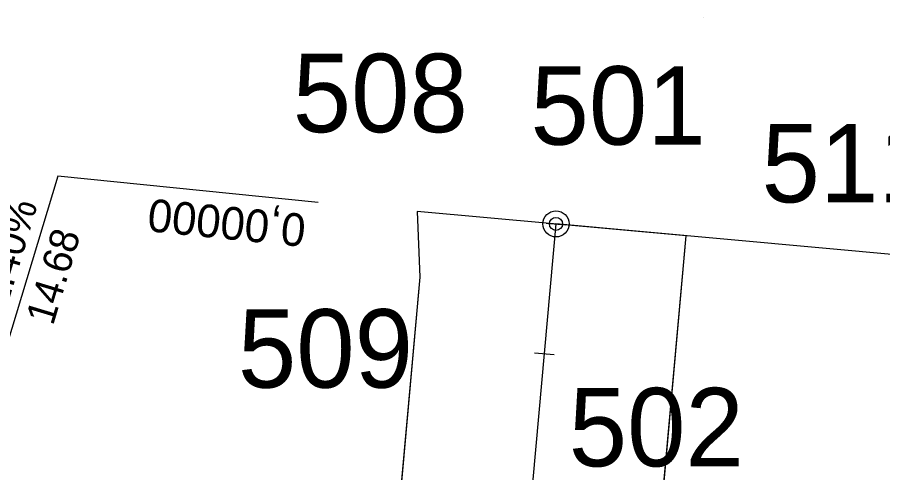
# Model space of a CAD drawing. Extents: x -747612 to -743169, y -1131726 to -1127091.
# Drawn here: x -747601.59 to -747588.36, y -1131700.57 to -1131693.61 of the extents above; entities that cross this region are included whole.
import ezdxf

# ---------------------------------------------------------------- set-up
doc = ezdxf.new("R2010")
doc.units = 0
for name, color, linetype in [('bublina_fialová_čára_tenká', 7, 'Continuous'), ('C3D_Trasa-Popisy trasy', 7, 'Continuous'), ('KOMUNIKACE_UPRAVA', 7, 'Continuous'), ('křížek', 7, 'Continuous'), ('OSA_KOMUNIKACE', 7, 'Continuous'), ('POP_OBLOUKY', 7, 'Continuous'), ('SKLONOVNIKY', 7, 'Continuous'), ('Vrstva 60', 7, 'Continuous')]:
    doc.layers.add(name, color=color, linetype=linetype)

# ---------------------------------------------------------------- blocks, each defined once
blk = doc.blocks.new('AeccTickCircle')
blk.add_circle((0, 0), 0.5)
blk = doc.blocks.new('POINT_DISPLAY')
blk.add_line((0, 0), (0, 0))

msp = doc.modelspace()

# ---------------------------------------------------------------- linework, layer by layer
at = {"layer": 'bublina_fialová_čára_tenká'}
msp.add_line((-747560.999, -1131699.707), (-747593.352, -1131696.768), dxfattribs=at)
at = {"layer": 'C3D_Trasa-Popisy trasy'}
for p, q in [((-747593.502, -1131696.755), (-747593.203, -1131696.782)), ((-747593.68, -1131698.739), (-747593.382, -1131698.766))]:
    msp.add_line(p, q, dxfattribs=at)
at = {"layer": 'KOMUNIKACE_UPRAVA'}
for p, q in [((-747591.36, -1131696.948), (-747595.475, -1131696.577)), ((-747595.475, -1131696.577), (-747595.434, -1131697.585)), ((-747592.053, -1131704.634), (-747591.36, -1131696.948)), ((-747595.434, -1131697.585), (-747595.983, -1131703.683))]:
    msp.add_line(p, q, dxfattribs=at)
msp.add_lwpolyline([(-747595.475, -1131696.577), (-747595.434, -1131697.585), (-747595.983, -1131703.683), (-747592.053, -1131704.634), (-747591.36, -1131696.948), (-747595.475, -1131696.577)], dxfattribs=at)
at = {"layer": 'OSA_KOMUNIKACE'}
msp.add_lwpolyline([(-747593.352, -1131696.768), (-747594.982, -1131714.85)], dxfattribs=at)
at = {"layer": 'SKLONOVNIKY'}
for p, q in [((-747600.968, -1131696.038), (-747601.835, -1131698.91)), ((-747596.989, -1131696.441), (-747600.968, -1131696.038))]:
    msp.add_line(p, q, dxfattribs=at)
at = {"layer": 'Vrstva 60'}
for p, q in [((-747595.475, -1131696.577), (-747595.475, -1131696.577)), ((-747593.352, -1131696.768), (-747593.352, -1131696.768)), ((-747591.36, -1131696.948), (-747591.36, -1131696.948)), ((-747595.434, -1131697.585), (-747595.434, -1131697.585)), ((-747593.531, -1131698.753), (-747593.531, -1131698.753))]:
    msp.add_line(p, q, dxfattribs=at)

# ---------------------------------------------------------------- block references
at = {"layer": 'křížek', "xscale": 10, "yscale": 10, "rotation": 61.14491455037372}
for p in [(-747591.089, -1131693.607), (-747595.475, -1131696.577), (-747593.352, -1131696.768), (-747591.36, -1131696.948), (-747595.434, -1131697.585), (-747593.531, -1131698.753)]:
    msp.add_blockref('POINT_DISPLAY', p, dxfattribs=at)
at = {"layer": 'POP_OBLOUKY', "rotation": -95.14959431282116}
for xscale, yscale in [(0.39999999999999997, 0.4), (0.19999999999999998, 0.2)]:
    msp.add_blockref('AeccTickCircle', (-747593.352, -1131696.768), dxfattribs=dict(at, xscale=xscale, yscale=yscale))

# ---------------------------------------------------------------- texts
at = {"layer": 'SKLONOVNIKY'}
for s, height, rotation, p in [('+2.40%', 0.44, 73.2181, (-747601.853, -1131698.397)), ('0,00000', 0.5, 174.2192, (-747597.158, -1131696.623)), ('14.68', 0.44, 73.2181, (-747601.043, -1131698.336))]:
    msp.add_text(s, height=height, rotation=rotation, dxfattribs=at).set_placement(p)
at = {"layer": 'Vrstva 60'}
for s, p in [('508', (-747597.377, -1131695.365)), ('501', (-747593.741, -1131695.556)), ('511', (-747590.209, -1131696.438)), ('509', (-747598.215, -1131699.273)), ('502', (-747593.157, -1131700.477))]:
    msp.add_text(s, height=1.2, dxfattribs=at).set_placement(p)

doc.saveas('drawing.dxf')
